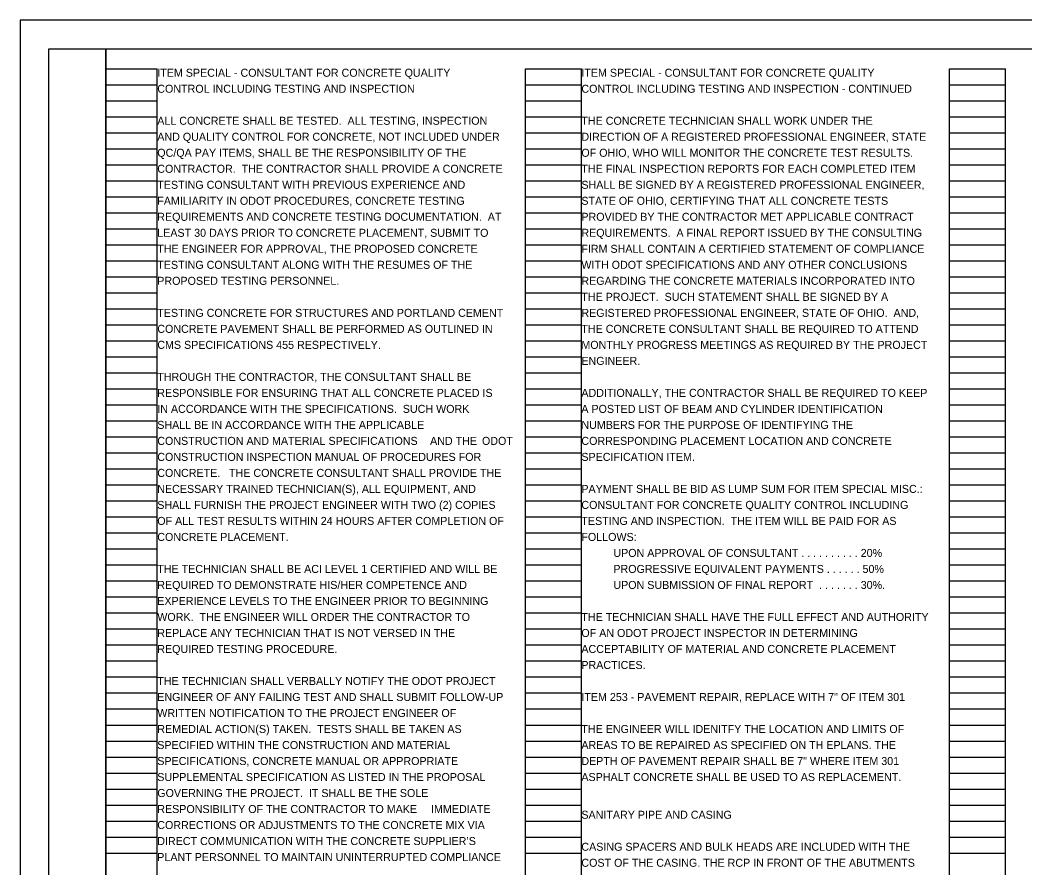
# Model space of a CAD drawing. Extents: x 0 to 34, y -7.4 to 22.
# Drawn here: x 0 to 17.58, y 7.17 to 22 of the extents above; entities that cross this region are included whole.
import ezdxf

# ---------------------------------------------------------------- set-up
doc = ezdxf.new("R2010")
doc.units = 0
for name, color, linetype in [('SH_Border', 7, 'Continuous'), ('SH_Cut_Line', 7, 'Continuous'), ('SH_Data', 7, 'Continuous'), ('SH_Text', 7, 'Continuous')]:
    doc.layers.add(name, color=color, linetype=linetype)

msp = doc.modelspace()

# ---------------------------------------------------------------- linework, layer by layer
at = {"layer": 'SH_Border'}
for points in [[(0.5, 21.5), (1.5, 21.5), (1.5, 0.5), (0.5, 0.5)], [(1.5, 21.5), (33.5, 21.5), (33.5, 0.5), (1.5, 0.5)]]:
    msp.add_lwpolyline(points, close=True, dxfattribs=at)
at = {"layer": 'SH_Cut_Line'}
msp.add_lwpolyline([(0, 0), (34, 0), (34, 22), (0, 22)], close=True, dxfattribs=at)
at = {"layer": 'SH_Data'}
for p, q in [((1.5, 0.989), (1.5, 21.149)), ((1.5, 21.149), (2.4, 21.149)), ((2.4, 0.989), (2.4, 21.149)), ((8.84, 0.989), (8.84, 21.149)), ((8.84, 21.149), (9.82, 21.149)), ((9.82, 0.989), (9.82, 21.149)), ((16.26, 0.989), (16.26, 21.149)), ((16.26, 21.149), (17.24, 21.149)), ((17.24, 0.989), (17.24, 21.149)), ((1.5, 20.869), (2.4, 20.869)), ((8.84, 20.869), (9.82, 20.869)), ((16.26, 20.869), (17.24, 20.869)), ((1.5, 20.589), (2.4, 20.589)), ((8.84, 20.589), (9.82, 20.589)), ((16.26, 20.589), (17.24, 20.589)), ((1.5, 20.309), (2.4, 20.309)), ((8.84, 20.309), (9.82, 20.309)), ((16.26, 20.309), (17.24, 20.309)), ((1.5, 20.029), (2.4, 20.029)), ((8.84, 20.029), (9.82, 20.029)), ((16.26, 20.029), (17.24, 20.029)), ((1.5, 19.749), (2.4, 19.749)), ((8.84, 19.749), (9.82, 19.749)), ((16.26, 19.749), (17.24, 19.749)), ((1.5, 19.469), (2.4, 19.469)), ((8.84, 19.469), (9.82, 19.469)), ((16.26, 19.469), (17.24, 19.469)), ((1.5, 19.189), (2.4, 19.189)), ((8.84, 19.189), (9.82, 19.189)), ((16.26, 19.189), (17.24, 19.189)), ((1.5, 18.909), (2.4, 18.909)), ((8.84, 18.909), (9.82, 18.909)), ((16.26, 18.909), (17.24, 18.909)), ((1.5, 18.629), (2.4, 18.629)), ((8.84, 18.629), (9.82, 18.629)), ((16.26, 18.629), (17.24, 18.629)), ((1.5, 18.349), (2.4, 18.349)), ((8.84, 18.349), (9.82, 18.349)), ((16.26, 18.349), (17.24, 18.349)), ((1.5, 18.069), (2.4, 18.069)), ((8.84, 18.069), (9.82, 18.069)), ((16.26, 18.069), (17.24, 18.069)), ((1.5, 17.789), (2.4, 17.789)), ((8.84, 17.789), (9.82, 17.789)), ((16.26, 17.789), (17.24, 17.789)), ((1.5, 17.509), (2.4, 17.509)), ((8.84, 17.509), (9.82, 17.509)), ((16.26, 17.509), (17.24, 17.509)), ((1.5, 17.229), (2.4, 17.229)), ((8.84, 17.229), (9.82, 17.229)), ((16.26, 17.229), (17.24, 17.229)), ((1.5, 16.949), (2.4, 16.949)), ((8.84, 16.949), (9.82, 16.949)), ((16.26, 16.949), (17.24, 16.949)), ((1.5, 16.669), (2.4, 16.669)), ((8.84, 16.669), (9.82, 16.669)), ((16.26, 16.669), (17.24, 16.669)), ((1.5, 16.389), (2.4, 16.389)), ((8.84, 16.389), (9.82, 16.389)), ((16.26, 16.389), (17.24, 16.389)), ((1.5, 16.109), (2.4, 16.109)), ((8.84, 16.109), (9.82, 16.109)), ((16.26, 16.109), (17.24, 16.109)), ((1.5, 15.829), (2.4, 15.829)), ((8.84, 15.829), (9.82, 15.829)), ((16.26, 15.829), (17.24, 15.829)), ((1.5, 15.549), (2.4, 15.549)), ((8.84, 15.549), (9.82, 15.549)), ((16.26, 15.549), (17.24, 15.549)), ((1.5, 15.269), (2.4, 15.269)), ((8.84, 15.269), (9.82, 15.269)), ((16.26, 15.269), (17.24, 15.269)), ((1.5, 14.989), (2.4, 14.989)), ((8.84, 14.989), (9.82, 14.989)), ((16.26, 14.989), (17.24, 14.989)), ((1.5, 14.709), (2.4, 14.709)), ((8.84, 14.709), (9.82, 14.709)), ((16.26, 14.709), (17.24, 14.709)), ((1.5, 14.429), (2.4, 14.429)), ((8.84, 14.429), (9.82, 14.429)), ((16.26, 14.429), (17.24, 14.429)), ((1.5, 14.149), (2.4, 14.149)), ((8.84, 14.149), (9.82, 14.149)), ((16.26, 14.149), (17.24, 14.149)), ((1.5, 13.869), (2.4, 13.869)), ((8.84, 13.869), (9.82, 13.869)), ((16.26, 13.869), (17.24, 13.869)), ((1.5, 13.589), (2.4, 13.589)), ((8.84, 13.589), (9.82, 13.589)), ((16.26, 13.589), (17.24, 13.589)), ((1.5, 13.309), (2.4, 13.309)), ((8.84, 13.309), (9.82, 13.309)), ((16.26, 13.309), (17.24, 13.309)), ((1.5, 13.029), (2.4, 13.029)), ((8.84, 13.029), (9.82, 13.029)), ((16.26, 13.029), (17.24, 13.029)), ((1.5, 12.749), (2.4, 12.749)), ((8.84, 12.749), (9.82, 12.749)), ((16.26, 12.749), (17.24, 12.749)), ((1.5, 12.469), (2.4, 12.469)), ((8.84, 12.469), (9.82, 12.469)), ((16.26, 12.469), (17.24, 12.469)), ((1.5, 12.189), (2.4, 12.189)), ((8.84, 12.189), (9.82, 12.189)), ((16.26, 12.189), (17.24, 12.189)), ((1.5, 11.909), (2.4, 11.909)), ((8.84, 11.909), (9.82, 11.909)), ((16.26, 11.909), (17.24, 11.909)), ((1.5, 11.629), (2.4, 11.629)), ((8.84, 11.629), (9.82, 11.629)), ((16.26, 11.629), (17.24, 11.629)), ((1.5, 11.349), (2.4, 11.349)), ((8.84, 11.349), (9.82, 11.349)), ((16.26, 11.349), (17.24, 11.349)), ((1.5, 11.069), (2.4, 11.069)), ((8.84, 11.069), (9.82, 11.069)), ((16.26, 11.069), (17.24, 11.069)), ((1.5, 10.789), (2.4, 10.789)), ((8.84, 10.789), (9.82, 10.789)), ((16.26, 10.789), (17.24, 10.789)), ((1.5, 10.509), (2.4, 10.509)), ((8.84, 10.509), (9.82, 10.509)), ((16.26, 10.509), (17.24, 10.509)), ((1.5, 10.229), (2.4, 10.229)), ((8.84, 10.229), (9.82, 10.229)), ((16.26, 10.229), (17.24, 10.229)), ((1.5, 9.949), (2.4, 9.949)), ((8.84, 9.949), (9.82, 9.949)), ((16.26, 9.949), (17.24, 9.949)), ((1.5, 9.669), (2.4, 9.669)), ((8.84, 9.669), (9.82, 9.669)), ((16.26, 9.669), (17.24, 9.669)), ((1.5, 9.389), (2.4, 9.389)), ((8.84, 9.389), (9.82, 9.389)), ((16.26, 9.389), (17.24, 9.389)), ((1.5, 9.109), (2.4, 9.109)), ((8.84, 9.109), (9.82, 9.109)), ((16.26, 9.109), (17.24, 9.109)), ((1.5, 8.829), (2.4, 8.829)), ((8.84, 8.829), (9.82, 8.829)), ((16.26, 8.829), (17.24, 8.829)), ((1.5, 8.549), (2.4, 8.549)), ((8.84, 8.549), (9.82, 8.549)), ((16.26, 8.549), (17.24, 8.549)), ((1.5, 8.269), (2.4, 8.269)), ((8.84, 8.269), (9.82, 8.269)), ((16.26, 8.269), (17.24, 8.269)), ((1.5, 7.989), (2.4, 7.989)), ((8.84, 7.989), (9.82, 7.989)), ((16.26, 7.989), (17.24, 7.989)), ((1.5, 7.709), (2.4, 7.709)), ((8.84, 7.709), (9.82, 7.709)), ((16.26, 7.709), (17.24, 7.709)), ((1.5, 7.429), (2.4, 7.429)), ((8.84, 7.429), (9.82, 7.429)), ((16.26, 7.429), (17.24, 7.429))]:
    msp.add_line(p, q, dxfattribs=at)

# ---------------------------------------------------------------- texts
at = {"layer": 'SH_Text'}
for s, p in [('ITEM SPECIAL - CONSULTANT FOR CONCRETE QUALITY ', (2.4, 21.009)), ('ITEM SPECIAL - CONSULTANT FOR CONCRETE QUALITY ', (9.82, 21.009)), ('CONTROL INCLUDING TESTING AND INSPECTION', (2.4, 20.729)), ('CONTROL INCLUDING TESTING AND INSPECTION - CONTINUED', (9.82, 20.729)), ('ALL CONCRETE SHALL BE TESTED.  ALL TESTING, INSPECTION ', (2.4, 20.169)), ('THE CONCRETE TECHNICIAN SHALL WORK UNDER THE ', (9.82, 20.169)), ('AND QUALITY CONTROL FOR CONCRETE, NOT INCLUDED UNDER ', (2.4, 19.889)), ('DIRECTION OF A REGISTERED PROFESSIONAL ENGINEER, STATE ', (9.82, 19.889)), ('QC/QA PAY ITEMS, SHALL BE THE RESPONSIBILITY OF THE ', (2.4, 19.609)), ('OF OHIO, WHO WILL MONITOR THE CONCRETE TEST RESULTS.  ', (9.82, 19.609)), ('CONTRACTOR.  THE CONTRACTOR SHALL PROVIDE A CONCRETE ', (2.4, 19.329)), ('THE FINAL INSPECTION REPORTS FOR EACH COMPLETED ITEM ', (9.82, 19.329)), ('TESTING CONSULTANT WITH PREVIOUS EXPERIENCE AND ', (2.4, 19.049)), ('SHALL BE SIGNED BY A REGISTERED PROFESSIONAL ENGINEER, ', (9.82, 19.049)), ('FAMILIARITY IN ODOT PROCEDURES, CONCRETE TESTING ', (2.4, 18.769)), ('STATE OF OHIO, CERTIFYING THAT ALL CONCRETE TESTS ', (9.82, 18.769)), ('REQUIREMENTS AND CONCRETE TESTING DOCUMENTATION.  AT ', (2.4, 18.489)), ('PROVIDED BY THE CONTRACTOR MET APPLICABLE CONTRACT ', (9.82, 18.489)), ('LEAST 30 DAYS PRIOR TO CONCRETE PLACEMENT, SUBMIT TO ', (2.4, 18.209)), ('REQUIREMENTS.  A FINAL REPORT ISSUED BY THE CONSULTING ', (9.82, 18.209)), ('THE ENGINEER FOR APPROVAL, THE PROPOSED CONCRETE ', (2.4, 17.929)), ('FIRM SHALL CONTAIN A CERTIFIED STATEMENT OF COMPLIANCE ', (9.82, 17.929)), ('TESTING CONSULTANT ALONG WITH THE RESUMES OF THE ', (2.4, 17.649)), ('WITH ODOT SPECIFICATIONS AND ANY OTHER CONCLUSIONS ', (9.82, 17.649)), ('PROPOSED TESTING PERSONNEL.  ', (2.4, 17.369)), ('REGARDING THE CONCRETE MATERIALS INCORPORATED INTO ', (9.82, 17.369)), ('THE PROJECT.  SUCH STATEMENT SHALL BE SIGNED BY A ', (9.82, 17.089)), ('TESTING CONCRETE FOR STRUCTURES AND PORTLAND CEMENT ', (2.4, 16.809)), ('REGISTERED PROFESSIONAL ENGINEER, STATE OF OHIO.  AND, ', (9.82, 16.809)), ('CONCRETE PAVEMENT SHALL BE PERFORMED AS OUTLINED IN ', (2.4, 16.529)), ('THE CONCRETE CONSULTANT SHALL BE REQUIRED TO ATTEND ', (9.82, 16.529)), ('CMS SPECIFICATIONS 455 RESPECTIVELY.', (2.4, 16.249)), ('MONTHLY PROGRESS MEETINGS AS REQUIRED BY THE PROJECT ', (9.82, 16.249)), ('ENGINEER.', (9.82, 15.969)), ('THROUGH THE CONTRACTOR, THE CONSULTANT SHALL BE ', (2.4, 15.689)), ('RESPONSIBLE FOR ENSURING THAT ALL CONCRETE PLACED IS ', (2.4, 15.409)), ('ADDITIONALLY, THE CONTRACTOR SHALL BE REQUIRED TO KEEP ', (9.82, 15.409)), ('IN ACCORDANCE WITH THE SPECIFICATIONS.  SUCH WORK ', (2.4, 15.129)), ('A POSTED LIST OF BEAM AND CYLINDER IDENTIFICATION ', (9.82, 15.129)), ('SHALL BE IN ACCORDANCE WITH THE APPLICABLE ', (2.4, 14.849)), ('NUMBERS FOR THE PURPOSE OF IDENTIFYING THE ', (9.82, 14.849)), ('CONSTRUCTION AND MATERIAL SPECIFICATIONS', (2.4, 14.569)), (' AND THE ', (7.121, 14.569)), ('ODOT ', (8.081, 14.569)), ('CORRESPONDING PLACEMENT LOCATION AND CONCRETE ', (9.82, 14.569)), ('CONSTRUCTION INSPECTION MANUAL OF PROCEDURES FOR ', (2.4, 14.289)), ('SPECIFICATION ITEM.', (9.82, 14.289)), ('CONCRETE.', (2.4, 14.009)), ('  THE CONCRETE CONSULTANT SHALL PROVIDE THE ', (3.552, 14.009)), ('NECESSARY TRAINED TECHNICIAN(S), ALL EQUIPMENT, AND ', (2.4, 13.729)), ('PAYMENT SHALL BE BID AS LUMP SUM FOR ITEM SPECIAL MISC.:  ', (9.82, 13.729)), ('SHALL FURNISH THE PROJECT ENGINEER WITH TWO (2) COPIES ', (2.4, 13.449)), ('CONSULTANT FOR CONCRETE QUALITY CONTROL INCLUDING ', (9.82, 13.449)), ('OF ALL TEST RESULTS WITHIN 24 HOURS AFTER COMPLETION OF ', (2.4, 13.169)), ('TESTING AND INSPECTION.  THE ITEM WILL BE PAID FOR AS ', (9.82, 13.169)), ('CONCRETE PLACEMENT.', (2.4, 12.889)), ('FOLLOWS:', (9.82, 12.889)), ('UPON APPROVAL OF CONSULTANT . . . . . . . . . . 20%', (10.38, 12.609)), ('THE TECHNICIAN SHALL BE ACI LEVEL 1 CERTIFIED AND WILL BE ', (2.4, 12.329)), ('PROGRESSIVE EQUIVALENT PAYMENTS . . . . . . 50%', (10.38, 12.329)), ('REQUIRED TO DEMONSTRATE HIS/HER COMPETENCE AND ', (2.4, 12.049)), ('UPON SUBMISSION OF FINAL REPORT  . . . . . . . 30%.', (10.38, 12.049)), ('EXPERIENCE LEVELS TO THE ENGINEER PRIOR TO BEGINNING ', (2.4, 11.769)), ('WORK.  THE ENGINEER WILL ORDER THE CONTRACTOR TO ', (2.4, 11.489)), ('THE TECHNICIAN SHALL HAVE THE FULL EFFECT AND AUTHORITY ', (9.82, 11.489)), ('REPLACE ANY TECHNICIAN THAT IS NOT VERSED IN THE ', (2.4, 11.209)), ('OF AN ODOT PROJECT INSPECTOR IN DETERMINING ', (9.82, 11.209)), ('REQUIRED TESTING PROCEDURE.', (2.4, 10.929)), ('ACCEPTABILITY OF MATERIAL AND CONCRETE PLACEMENT ', (9.82, 10.929)), ('PRACTICES.', (9.82, 10.649)), ('THE TECHNICIAN SHALL VERBALLY NOTIFY THE ODOT PROJECT ', (2.4, 10.369)), ('ENGINEER OF ANY FAILING TEST AND SHALL SUBMIT FOLLOW-UP ', (2.4, 10.089)), ('ITEM 253 - PAVEMENT REPAIR, REPLACE WITH 7" OF ITEM 301', (9.82, 10.089)), ('WRITTEN NOTIFICATION TO THE PROJECT ENGINEER OF ', (2.4, 9.809)), ('REMEDIAL ACTION(S) TAKEN.  TESTS SHALL BE TAKEN AS ', (2.4, 9.529)), ('THE ENGINEER WILL IDENITFY THE LOCATION AND LIMITS OF ', (9.82, 9.529)), ('SPECIFIED WITHIN THE CONSTRUCTION AND MATERIAL ', (2.4, 9.249)), ('AREAS TO BE REPAIRED AS SPECIFIED ON TH EPLANS. THE ', (9.82, 9.249)), ('SPECIFICATIONS, CONCRETE MANUAL OR APPROPRIATE ', (2.4, 8.969)), ('DEPTH OF PAVEMENT REPAIR SHALL BE 7" WHERE ITEM 301 ', (9.82, 8.969)), ('SUPPLEMENTAL SPECIFICATION AS LISTED IN THE PROPOSAL ', (2.4, 8.689)), ('ASPHALT CONCRETE SHALL BE USED TO AS REPLACEMENT.', (9.82, 8.689)), ('GOVERNING THE PROJECT.  IT SHALL BE THE SOLE ', (2.4, 8.409)), ('RESPONSIBILITY OF THE CONTRACTOR TO MAKE ', (2.4, 8.129)), ('IMMEDIATE', (7.19, 8.129)), ('SANITARY PIPE AND CASING', (9.82, 8.029)), ('CORRECTIONS OR ADJUSTMENTS TO THE CONCRETE MIX VIA ', (2.4, 7.849)), ('DIRECT COMMUNICATION WITH THE CONCRETE SUPPLIER’S ', (2.4, 7.569)), ('CASING SPACERS AND BULK HEADS ARE INCLUDED WITH THE ', (9.82, 7.469)), ('PLANT PERSONNEL TO MAINTAIN UNINTERRUPTED COMPLIANCE ', (2.4, 7.289)), ('COST OF THE CASING. THE RCP IN FRONT OF THE ABUTMENTS ', (9.82, 7.189))]:
    msp.add_text(s, height=0.14, dxfattribs=at).set_placement(p)

doc.saveas('drawing.dxf')
